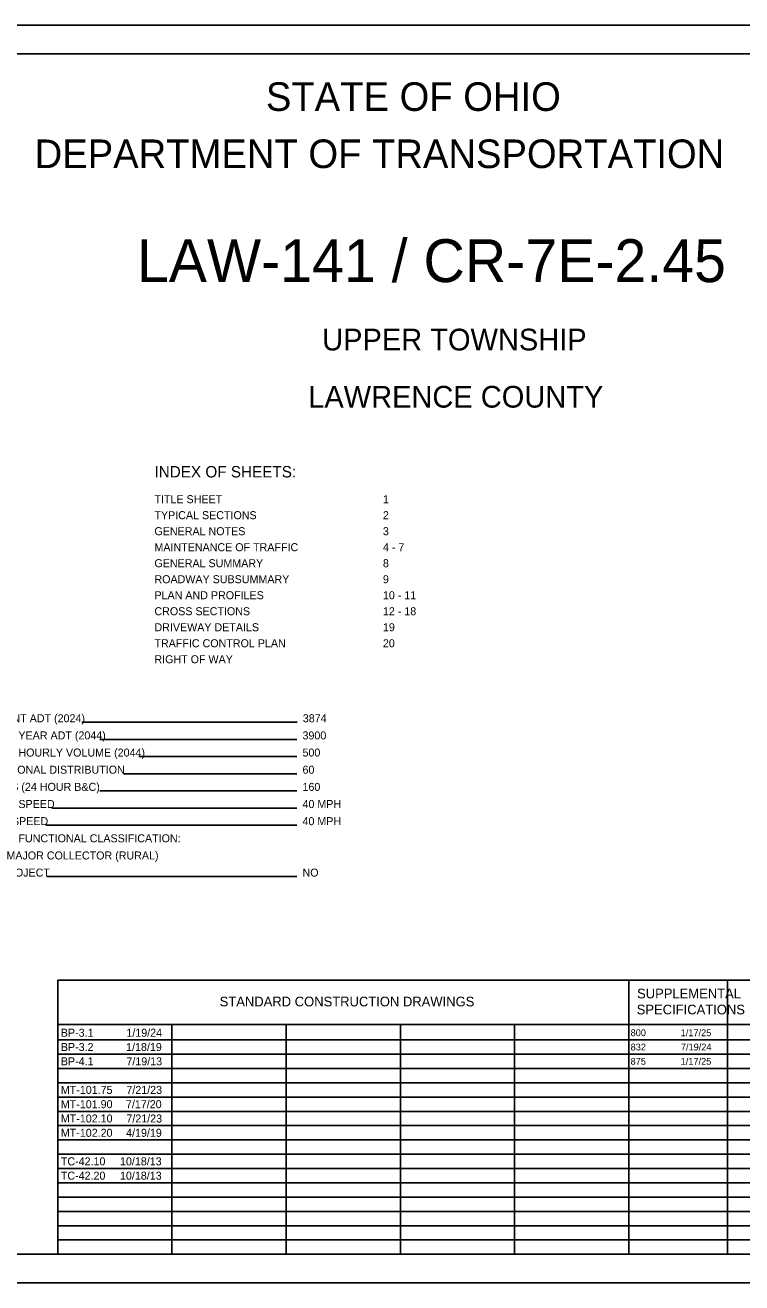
# Model space of a CAD drawing. Extents: x 0 to 34, y 0 to 22.
# Drawn here: x 9.58 to 22.13, y 0 to 22 of the extents above; entities that cross this region are included whole.
import ezdxf

# ---------------------------------------------------------------- set-up
doc = ezdxf.new("R2010")
doc.units = 0
for name, color, linetype in [('SH_Border', 7, 'Continuous'), ('SH_Data', 7, 'Continuous'), ('SH_Text', 7, 'Continuous')]:
    doc.layers.add(name, color=color, linetype=linetype)

msp = doc.modelspace()

# ---------------------------------------------------------------- linework, layer by layer
at = {"layer": 'SH_Border'}
msp.add_lwpolyline([(1.5, 21.5), (33.5, 21.5), (33.5, 0.5), (1.5, 0.5)], close=True, dxfattribs=at)
at = {"layer": 'SH_Data'}
for p, q in [((14.341, 9.806), (10.57, 9.806)), ((14.336, 9.506), (10.888, 9.506)), ((14.336, 9.206), (11.571, 9.206)), ((14.336, 8.906), (11.303, 8.906)), ((14.336, 8.606), (10.888, 8.606)), ((14.336, 8.306), (10.045, 8.306)), ((14.336, 8.006), (9.941, 8.006)), ((14.336, 7.106), (9.966, 7.106)), ((10.15, 5.292), (23.6, 5.292)), ((10.15, 0.5), (10.15, 5.292)), ((20.15, 0.5), (20.15, 5.292)), ((21.875, 0.5), (21.875, 5.292)), ((10.15, 4.521), (23.6, 4.521)), ((12.15, 0.5), (12.15, 4.521)), ((14.15, 0.5), (14.15, 4.521)), ((16.15, 0.5), (16.15, 4.521)), ((18.15, 0.5), (18.15, 4.521)), ((10.15, 4.25), (23.6, 4.25)), ((10.15, 4), (23.6, 4)), ((10.15, 3.75), (23.6, 3.75)), ((10.15, 3.5), (23.6, 3.5)), ((10.15, 3.25), (23.6, 3.25)), ((10.15, 3), (23.6, 3)), ((10.15, 2.75), (23.6, 2.75)), ((10.15, 2.5), (23.6, 2.5)), ((10.15, 2.25), (23.6, 2.25)), ((10.15, 2), (23.6, 2)), ((10.15, 1.75), (23.6, 1.75)), ((10.15, 1.5), (23.6, 1.5)), ((10.15, 1.25), (23.6, 1.25)), ((10.15, 1), (23.6, 1)), ((10.15, 0.75), (23.6, 0.75))]:
    msp.add_line(p, q, dxfattribs=at)
msp.add_lwpolyline([(0, 0), (34, 0), (34, 22), (0, 22)], close=True, dxfattribs=at)

# ---------------------------------------------------------------- texts
at = {"layer": 'SH_Text'}
for s, height, p in [('STATE OF OHIO', 0.5, (13.795, 20.5)), ('DEPARTMENT OF TRANSPORTATION', 0.5, (9.747, 19.5)), ('LAW-141 / CR-7E-2.45', 0.75, (11.537, 17.505)), ('UPPER TOWNSHIP', 0.38, (14.78, 16.31)), ('LAWRENCE COUNTY', 0.38, (14.536, 15.31)), ('INDEX OF SHEETS:', 0.2, (11.844, 14.088)), ('TITLE SHEET', 0.14, (11.844, 13.638)), ('1', 0.14, (15.844, 13.638)), ('TYPICAL SECTIONS', 0.14, (11.844, 13.358)), ('2', 0.14, (15.844, 13.358)), ('GENERAL NOTES', 0.14, (11.844, 13.078)), ('3', 0.14, (15.844, 13.078)), ('MAINTENANCE OF TRAFFIC', 0.14, (11.844, 12.798)), ('4 - 7', 0.14, (15.844, 12.798)), ('GENERAL SUMMARY', 0.14, (11.844, 12.518)), ('8', 0.14, (15.844, 12.518)), ('ROADWAY SUBSUMMARY', 0.14, (11.844, 12.238)), ('9', 0.14, (15.844, 12.238)), ('PLAN AND PROFILES', 0.14, (11.844, 11.958)), ('10 - 11', 0.14, (15.844, 11.958)), ('CROSS SECTIONS', 0.14, (11.844, 11.678)), ('12 - 18', 0.14, (15.844, 11.678)), ('DRIVEWAY DETAILS', 0.14, (11.844, 11.398)), ('19', 0.14, (15.844, 11.398)), ('TRAFFIC CONTROL PLAN', 0.14, (11.844, 11.118)), ('20', 0.14, (15.844, 11.118)), ('RIGHT OF WAY', 0.14, (11.844, 10.838)), ('CURRENT ADT (2024)', 0.14, (8.693, 9.806)), ('3874', 0.14, (14.441, 9.806)), ('DESIGN YEAR ADT (2044)', 0.14, (8.693, 9.506)), ('3900', 0.14, (14.436, 9.506)), ('DESIGN HOURLY VOLUME (2044)', 0.14, (8.693, 9.206)), ('500', 0.14, (14.436, 9.206)), ('DIRECTIONAL DISTRIBUTION', 0.14, (8.693, 8.906)), ('60', 0.14, (14.436, 8.906)), ('TRUCKS (24 HOUR B&C)', 0.14, (8.693, 8.606)), ('160', 0.14, (14.436, 8.606)), ('DESIGN SPEED', 0.14, (8.693, 8.306)), ('40 MPH', 0.14, (14.436, 8.306)), ('LEGAL SPEED', 0.14, (8.693, 8.006)), ('40 MPH', 0.14, (14.436, 8.006)), ('DESIGN FUNCTIONAL CLASSIFICATION:', 0.14, (8.693, 7.706)), ('MAJOR COLLECTOR (RURAL)', 0.14, (9.253, 7.406)), ('NHS PROJECT', 0.14, (8.693, 7.106)), ('NO', 0.14, (14.436, 7.106)), ('SUPPLEMENTAL', 0.17, (20.293, 4.976)), ('STANDARD CONSTRUCTION DRAWINGS', 0.17, (12.986, 4.836)), ('SPECIFICATIONS', 0.17, (20.287, 4.696)), ('BP-3.1', 0.14, (10.205, 4.305)), ('1/19/24', 0.14, (11.353, 4.305)), ('800', 0.12, (20.18, 4.315)), ('1/17/25', 0.12, (21.057, 4.315)), ('BP-3.2', 0.14, (10.205, 4.055)), ('1/18/19', 0.14, (11.348, 4.055)), ('832', 0.12, (20.18, 4.065)), ('7/19/24', 0.12, (21.06, 4.065)), ('BP-4.1', 0.14, (10.205, 3.805)), ('7/19/13', 0.14, (11.353, 3.805)), ('875', 0.12, (20.18, 3.815)), ('1/17/25', 0.12, (21.057, 3.815)), ('MT-101.75', 0.14, (10.205, 3.305)), ('7/21/23', 0.14, (11.353, 3.305)), ('MT-101.90', 0.14, (10.205, 3.055)), ('7/17/20', 0.14, (11.345, 3.055)), ('MT-102.10', 0.14, (10.205, 2.805)), ('7/21/23', 0.14, (11.353, 2.805)), ('MT-102.20', 0.14, (10.205, 2.555)), ('4/19/19', 0.14, (11.348, 2.555)), ('10/18/13', 0.14, (11.241, 2.055)), ('TC-42.10', 0.14, (10.205, 2.055)), ('TC-42.20', 0.14, (10.205, 1.805)), ('10/18/13', 0.14, (11.241, 1.805))]:
    msp.add_text(s, height=height, dxfattribs=at).set_placement(p)

doc.saveas('drawing.dxf')
